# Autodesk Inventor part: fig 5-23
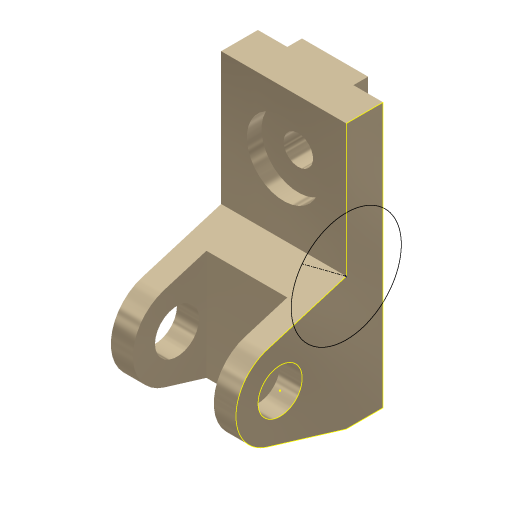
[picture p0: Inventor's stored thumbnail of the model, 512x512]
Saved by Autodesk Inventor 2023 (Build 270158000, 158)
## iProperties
Created: 2001-11
Part Number: fig 5-23
Document SubType Name: Modeling
Designer: Renu Muthoo
Density: 1 g/cm^3
Material: Generic
Appearance: Metal-Titanium (Polished)
Control State: 0
Master: False
Checked Out: False
Shininess: 65.0
Angle Display Precision: 2
Document Length Units: 11269
Document Angle Units: 11279
Document Time Units: 11290
Document Mass Units: 11283
Document Length Units Precision: 3
Document Angle Units Precision: 2
Compacted: False
Density: 0.0
Volumn: 0.0
Area: 0.0
PropertySet Name: Model Information
Author: Renu Muthoo
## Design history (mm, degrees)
node "Sketch1"
sketch "Sketch2"
  geometry: L1 (33.257, 104.664)-(33.257, -75.336); L2 (33.257, -75.336)-(8.257, -75.336); L3 (8.257, -75.336)-(-45.451, -59.045); L4 (-45.451, -1.628)-(8.257, 14.664); L5 (8.257, 14.664)-(8.257, 104.664); L6 (8.257, 104.664)-(33.257, 104.664); C1 r 15 at (-36.743, -30.336); A1 r 30 centre (-36.743, -30.336) between (-45.451, -1.628) and (-45.451, -59.045)
  constraints: 12 end point, 2 centre point, 2 equal length, 2 parallel, 2 point on circle, 2 tangent, 1 coincident, 1 perpendicular, 1 vertical
  dimensions: "d0" = 180 distance of L1.start L1.end; "d1" = 30 radius of A1; "d2" = 25 distance of L5.end L1.start; "d3" = 45 distance from line of L2 A1.centre; "d4" = 70 distance from line of L1 A1.centre; "d5" = 30 diameter of C1
extrude "Extrusion1" new body sketch "Sketch2" distance "d6" = 85; taper "d7" = 0 deg
workplane "Work Plane1"
sketch "Sketch3"
  geometry: L1 (15, 62.364)-(70, 62.364); L2 (70, 62.364)-(70, -52.386); L3 (70, -52.386)-(15, -52.386); L4 (15, -52.386)-(15, 62.364); L5 (0, -45)-(0, -28.708) reference
  constraints: 8 end point, 2 parallel, 1 horizontal, 1 perpendicular
  dimensions: "d8" = 55 distance of L1.start L1.end; "d9" = 15 distance between parallel lines of L5 L4
extrude "Extrusion2" cut sketch "Sketch3" distance "d10" = 50; taper "d11" = 0 deg
sketch "Sketch4"
  geometry: L1 (0, 25)-(85, 25) reference; L2 (0, 0)-(0, 25) reference; L3 (20, 25)-(65, 25); L4 (65, 25)-(65, 35); L5 (65, 35)-(20, 35); L6 (20, 35)-(20, 25)
  constraints: 8 end point, 2 parallel, 1 horizontal, 1 perpendicular, 1 point on line
  dimensions: "d12" = 45 distance of L4.end L5.end; "d13" = 10 distance of L3.end L4.end; "d14" = 20 distance between parallel lines of L2 L6
extrude "Extrusion3" join sketch "Sketch4" stored distance "d15" = 50; taper "d16" = 0 deg
sketch "Sketch5"
  geometry: L1 (85, 0)-(85, 90) reference; L2 (0, 90)-(85, 90) reference; 1 further point
  dimensions: "d17" = 42 distance from line of L2 point (42.5, 48); "d18" = 42.5 distance from line of L1 point (42.5, 48)
hole "Hole1" sketch "Sketch5" at (42.5, 48) diameter "d19" = 20; stored, may be unused: countersink angle "d23" = 82 deg, drill point angle "d25" = 118 deg; dims "d20" = 6, "d21" = 50, "d22" = 10, "d24" = 8
sketch "Sketch8"
  geometry: L1 (75.336, 33.257)-(75.336, 8.257) reference; L2 (-104.664, 33.257)-(75.336, 33.257) reference; L3 (-104.664, 8.257)-(-104.664, 33.257) reference; L4 (-14.664, 8.257)-(-104.664, 8.257) reference; L5 (1.628, -45.451)-(-14.664, 8.257) reference; L6 (75.336, 8.257)-(59.045, -45.451) reference; C1 r 15 at (30.336, -36.743) reference; C2 r 37.437 at (-14.664, 8.257); A1 r 30 centre (30.336, -36.743) between (1.628, -45.451) and (59.045, -45.451) reference
  constraints: 1 centre point, 1 coincident
sketch "Sketch9"
  geometry: L1 (75.336, 33.257)-(75.336, 8.257) reference; L2 (-14.664, 8.257)-(-104.664, 8.257) reference; L3 (1.628, -45.451)-(-14.664, 8.257) reference; L4 (75.336, 8.257)-(59.045, -45.451) reference; L5 (-14.664, 8.257)-(-37, -21.743); C1 r 15 at (30.336, -36.743) reference; A1 r 30 centre (30.336, -36.743) between (1.628, -45.451) and (59.045, -45.451) reference
  constraints: 2 end point
body "Solid1"
